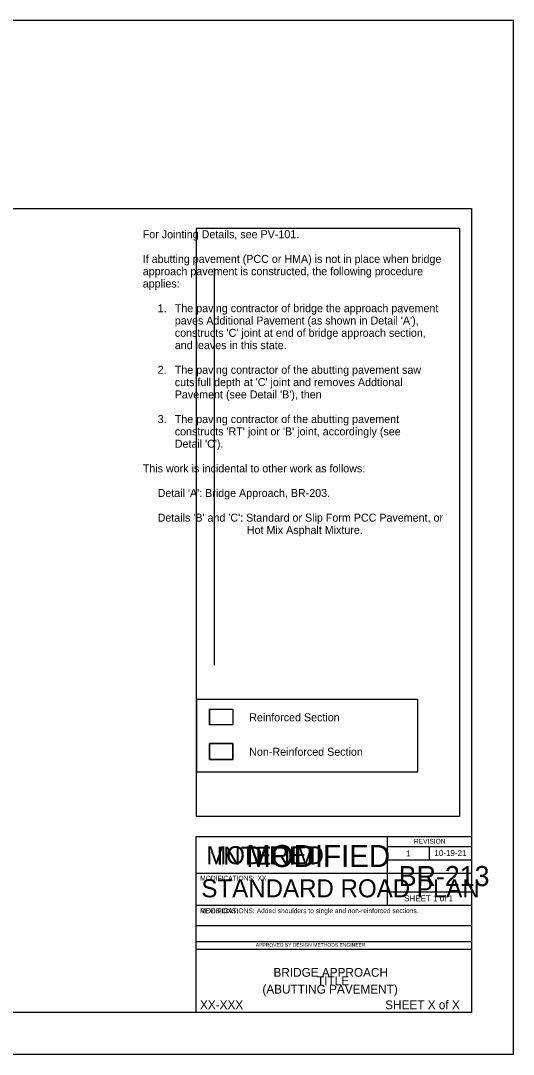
# Model space of a CAD drawing. Extents: x -2135039 to -2131695, y -2139150 to -2136566.
# Drawn here: x -2132926 to -2131695, y -2139150 to -2136566 of the extents above; entities that cross this region are included whole.
import ezdxf

# ---------------------------------------------------------------- set-up
doc = ezdxf.new("R2010")
doc.units = 0
for name, color, linetype in [('dsnDOTLogo', 7, 'Continuous'), ('dsnNonPlotable', 7, 'Continuous'), ('dsnStdBlock', 7, 'Continuous'), ('dsnstdblockInterim', 7, 'Continuous'), ('dsnStdLogo', 7, 'Continuous'), ('dsnstdModifiedBlock', 7, 'Continuous'), ('Level 1', 7, 'Continuous'), ('Level 2', 7, 'Continuous'), ('Level 3', 7, 'Continuous'), ('Level 8', 7, 'Continuous')]:
    doc.layers.add(name, color=color, linetype=linetype)

msp = doc.modelspace()

# ---------------------------------------------------------------- linework, layer by layer
at = {"layer": 'dsnDOTLogo'}
msp.add_lwpolyline([(-2135038.9, -2139150.4), (-2131694.9, -2139150.4), (-2131694.9, -2136566.4), (-2135038.9, -2136566.4)], close=True, dxfattribs=at)
at = {"layer": 'dsnNonPlotable'}
for p, q in [((-2132487.5, -2137085.9), (-2132487.5, -2138555.9)), ((-2131829.4, -2137085.9), (-2132487.5, -2137085.9)), ((-2131829.4, -2137085.9), (-2131829.4, -2138555.9)), ((-2132442.5, -2137185.9), (-2132442.5, -2138177.5)), ((-2131829.4, -2138555.9), (-2132487.5, -2138555.9))]:
    msp.add_line(p, q, dxfattribs=at)
at = {"layer": 'dsnStdLogo'}
for p, q in [((-2132010.4, -2138605.9), (-2132010.4, -2138697.3)), ((-2132010.4, -2138630.9), (-2131799.4, -2138630.9)), ((-2131904.9, -2138630.9), (-2131904.9, -2138664.1)), ((-2132010.4, -2138664.1), (-2131799.4, -2138664.1)), ((-2132487.5, -2138697.3), (-2132010.4, -2138697.3)), ((-2132010.4, -2138697.3), (-2132010.4, -2138777.3)), ((-2131799.4, -2138745.1), (-2132010.4, -2138745.1)), ((-2132487.5, -2138777.3), (-2131799.4, -2138777.3)), ((-2132487.5, -2138828.3), (-2131799.4, -2138828.3)), ((-2132487.5, -2138868.3), (-2131799.4, -2138868.3)), ((-2132487.5, -2138887.3), (-2131799.4, -2138887.3))]:
    msp.add_line(p, q, dxfattribs=at)
msp.add_lwpolyline([(-2132487.5, -2138605.9), (-2131799.4, -2138605.9), (-2131799.4, -2139045.9), (-2132487.5, -2139045.9)], close=True, dxfattribs=at)
at = {"layer": 'dsnstdModifiedBlock'}
for p, q in [((-2132487.5, -2138697.3), (-2131799.4, -2138697.3)), ((-2132487.5, -2138887.3), (-2131799.4, -2138887.3))]:
    msp.add_line(p, q, dxfattribs=at)
msp.add_lwpolyline([(-2132487.5, -2138605.9), (-2131799.4, -2138605.9), (-2131799.4, -2139045.9), (-2132487.5, -2139045.9)], close=True, dxfattribs=at)
at = {"layer": 'Level 1'}
msp.add_lwpolyline([(-2134934.4, -2137035.9), (-2131799.4, -2137035.9), (-2131799.4, -2139045.9), (-2134934.4, -2139045.9)], close=True, dxfattribs=at)
at = {"layer": 'Level 2'}
for p, q in [((-2132453.9, -2138287.4), (-2132395.8, -2138287.4)), ((-2132453.9, -2138287.4), (-2132453.9, -2138326.8)), ((-2132395.8, -2138287.4), (-2132395.8, -2138326.8)), ((-2132395.8, -2138326.8), (-2132453.9, -2138326.8))]:
    msp.add_line(p, q, dxfattribs=at)
for points in [[(-2132485.7, -2138263), (-2131934, -2138263), (-2131934, -2138444.9), (-2132485.7, -2138444.9)], [(-2132453.9, -2138373.7), (-2132395.8, -2138373.7), (-2132395.8, -2138413), (-2132453.9, -2138413)]]:
    msp.add_lwpolyline(points, close=True, dxfattribs=at)
msp.add_lwpolyline([(-2132453.9, -2138413), (-2132395.8, -2138413), (-2132395.8, -2138373.7), (-2132453.9, -2138373.7), (-2132453.9, -2138413)], dxfattribs=at)
at = {"layer": 'Level 3'}
for p, q in [((-2132453.9, -2138287.4), (-2132395.8, -2138287.4)), ((-2132453.9, -2138326.8), (-2132453.9, -2138287.4)), ((-2132395.8, -2138287.4), (-2132395.8, -2138326.8)), ((-2132395.8, -2138326.8), (-2132453.9, -2138326.8))]:
    msp.add_line(p, q, dxfattribs=at)

# ---------------------------------------------------------------- texts
at = {"layer": 'dsnNonPlotable'}
msp.add_text('REVISIONS:', height=12, dxfattribs=at).set_placement((-2132477.5, -2138797.6))
at = {"layer": 'dsnStdBlock'}
for s, height, p in [('MODIFIED', 45, (-2132462.4, -2138675.1)), ('MODIFICATIONS:', 12, (-2132477.5, -2138797.6))]:
    msp.add_text(s, height=height, dxfattribs=at).set_placement(p)
at = {"layer": 'dsnstdblockInterim'}
msp.add_text('INTERIM', height=45, dxfattribs=at).set_placement((-2132436.5, -2138676.3))
at = {"layer": 'dsnStdLogo'}
for s, height, p in [('REVISION', 12, (-2131943.4, -2138623.8)), ('1', 15, (-2131962.6, -2138655.3)), ('10-19-21', 15, (-2131892.2, -2138654.8)), ('BR-213', 50, (-2131981.2, -2138729.8)), ('STANDARD ROAD PLAN', 45.001, (-2132474.4, -2138757.9)), ('SHEET 1 of 1', 15, (-2131968, -2138767.9)), ('Added shoulders to single and non-reinforced sections.', 12, (-2132336.1, -2138797.5)), ('APPROVED BY DESIGN METHODS ENGINEER', 9.003, (-2132338.5, -2138881.4)), ('BRIDGE APPROACH', 22, (-2132294.3, -2138956.6)), ('(ABUTTING PAVEMENT)', 22, (-2132322, -2138998.6))]:
    msp.add_text(s, height=height, dxfattribs=at).set_placement(p)
at = {"layer": 'dsnstdModifiedBlock'}
for s, height, p in [('MODIFIED', 55, (-2132362.4, -2138682.2)), ('MODIFICATIONS:', 12, (-2132477.5, -2138716.1)), ('XX', 12, (-2132334.2, -2138716.1)), ('TITLE', 22, (-2132185.4, -2138977.6)), ('XX-XXX', 22, (-2132477.9, -2139037.6)), ('SHEET X of X', 22, (-2132015.1, -2139037.6))]:
    msp.add_text(s, height=height, dxfattribs=at).set_placement(p)
at = {"layer": 'Level 3'}
for s, p in [('Reinforced Section', (-2132354.9, -2138317.9)), ('Non-Reinforced Section', (-2132354.9, -2138404.1))]:
    msp.add_text(s, height=20, dxfattribs=at).set_placement(p)
at = {"layer": 'Level 8'}
for s, p in [('For Jointing Details, see PV-101.', (-2132620.9, -2137110.4)), ('If abutting pavement (PCC or HMA) is not in place when bridge', (-2132620.9, -2137172)), ('approach pavement is constructed, the following procedure', (-2132620.9, -2137202.8)), ('applies:', (-2132620.9, -2137233.6)), ('     1.', (-2132620.9, -2137295.2)), ('The paving contractor of bridge the approach pavement', (-2132540.9, -2137295.2)), ("paves Additional Pavement (as shown in Detail 'A'), ", (-2132540.9, -2137326)), ("constructs 'C' joint at end of bridge approach section,", (-2132540.9, -2137356.8)), ('and leaves in this state.', (-2132540.9, -2137387.6)), ('The paving contractor of the abutting pavement saw', (-2132540.9, -2137449.2)), ('     2.', (-2132620.9, -2137449.2)), ("cuts full depth at 'C' joint and removes Addtional", (-2132540.9, -2137480)), ("Pavement (see Detail 'B'), then", (-2132540.9, -2137510.8)), ('     3.', (-2132620.9, -2137572.4)), ('The paving contractor of the abutting pavement', (-2132540.9, -2137572.4)), ("constructs 'RT' joint or 'B' joint, accordingly (see", (-2132540.9, -2137603.2)), ("Detail 'C').", (-2132540.9, -2137634)), ('This work is incidental to other work as follows:', (-2132620.9, -2137695.6)), ("     Detail 'A': Bridge Approach, BR-203.", (-2132620.9, -2137757.2)), ("     Details 'B' and 'C': Standard or Slip Form PCC Pavement, or", (-2132620.9, -2137818.8)), ('                                   Hot Mix Asphalt Mixture.', (-2132620.9, -2137849.6))]:
    msp.add_text(s, height=20, dxfattribs=at).set_placement(p)

doc.saveas('drawing.dxf')
